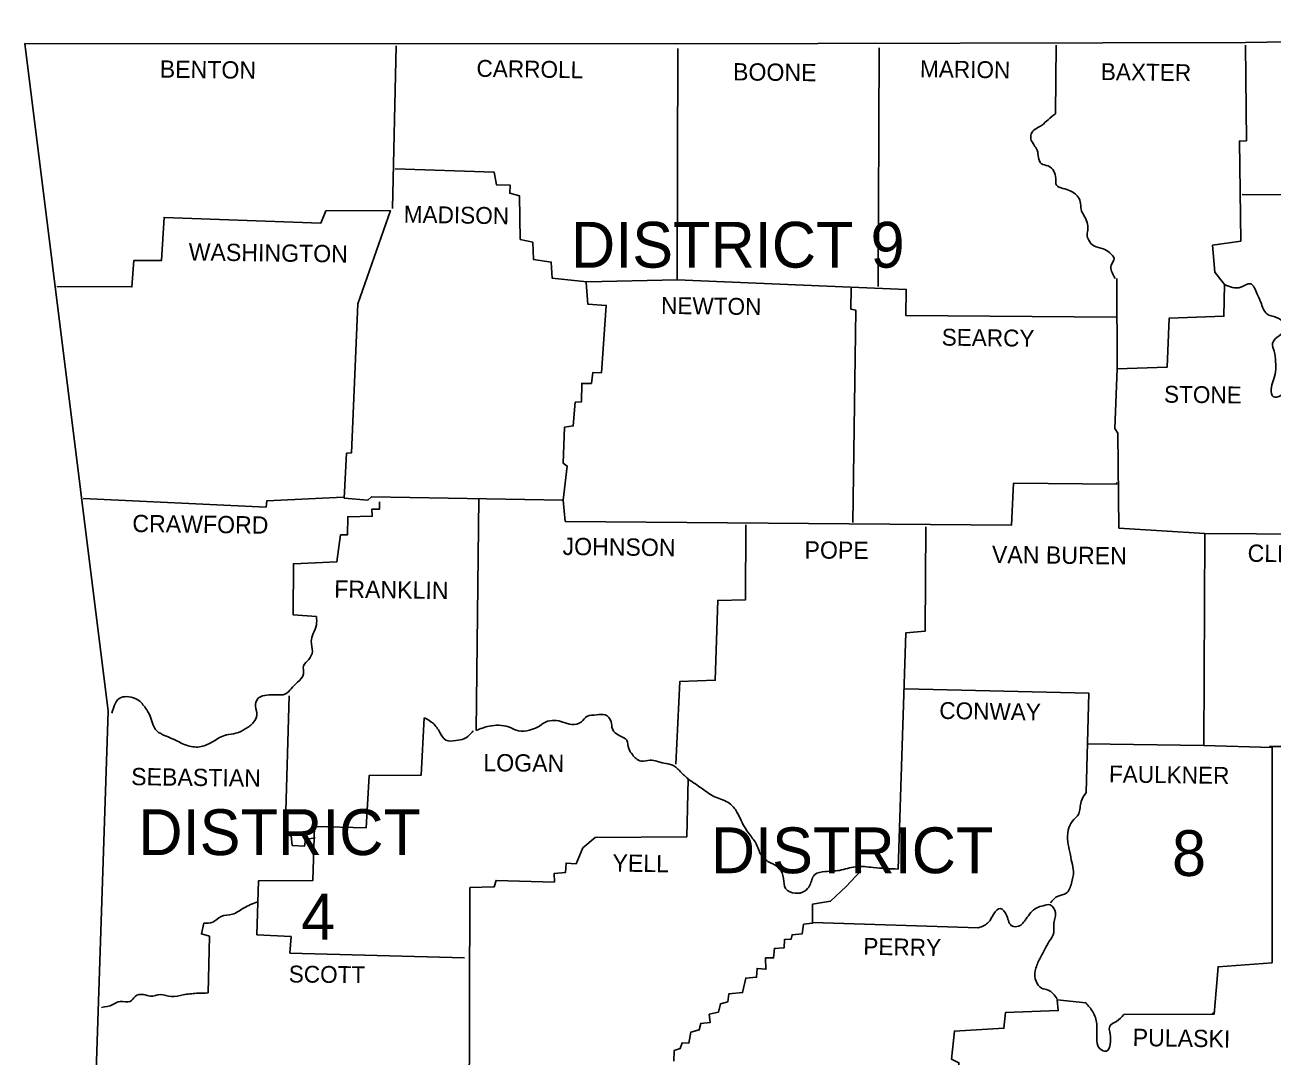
# Model space of a CAD drawing. Extents: x -33639 to 34530, y -17264 to 5867.
# Drawn here: x -17668 to -15961, y 4454 to 5867 of the extents above; entities that cross this region are included whole.
import ezdxf

# ---------------------------------------------------------------- set-up
doc = ezdxf.new("R2010")
doc.units = 0
for name, color, linetype in [('1', 7, 'Continuous'), ('2', 7, 'Continuous'), ('3', 7, 'Continuous')]:
    doc.layers.add(name, color=color, linetype=linetype)

msp = doc.modelspace()

# ---------------------------------------------------------------- linework, layer by layer
at = {"layer": '1'}
for points in [[(-17667.8, 5841.4), (-16777.9, 5840.9), (-15996.9, 5842.5), (-15075.6, 5856.8), (-14648.6, 5866.7)], [(-17667.8, 5841.4), (-17553.9, 4926.7), (-17603.4, 3433.6)], [(-16256.1, 5839.2), (-16257.2, 5745.1)], [(-15996.9, 5839.2), (-15995.8, 5708.2), (-16005.2, 5707.7), (-16003.5, 5570.7), (-16042.1, 5565.2), (-16038.8, 5528.3), (-16025.5, 5511.2), (-16026.6, 5467.7), (-16101.5, 5465), (-16104.2, 5397.8), (-16172.5, 5395.6), (-16175.8, 5314.2), (-16171.9, 5307.6), (-16170.3, 5177.7), (-16052.5, 5170), (-16054.2, 4880), (-15960.6, 4877.2), (-15960.6, 4582.2), (-16034.4, 4576.7), (-16039.9, 4511.8), (-16163.7, 4511.2)], [(-15530.8, 5847.5), (-15529.7, 5711), (-15601.2, 5707.1), (-15603.4, 5632.3), (-16001.3, 5634.5)], [(-17159.8, 5838.1), (-17164.8, 5615.2)], [(-17160.9, 5669.7), (-17025.5, 5665.3), (-17022.2, 5647.7), (-17003.5, 5647.2), (-17004.1, 5636.1), (-16990.9, 5632.8), (-16989.8, 5572.9), (-16972.7, 5569), (-16971.6, 5545.3), (-16947.4, 5542), (-16946.3, 5520), (-16898.4, 5515.1), (-16775.1, 5517.8), (-16774, 5834.3)], [(-16498.3, 5835.4), (-16500, 5508.5)], [(-17624.3, 5508.5), (-17521.4, 5507.9), (-17518.7, 5544.2), (-17480.7, 5544.2), (-17477.4, 5603.1), (-17262.7, 5595.4), (-17256.1, 5611.9), (-17167.5, 5612.5), (-17212.1, 5484.8), (-17220.9, 5280.6), (-17227.5, 5280.1), (-17230.8, 5218.4), (-17198.4, 5215.7), (-17193.4, 5220.6), (-16930.9, 5215.7), (-16928.1, 5186.5)], [(-16775.1, 5517.8), (-16461.4, 5504.6), (-16462, 5468.8), (-16174.1, 5466.6)], [(-16172.5, 5395.6), (-16173, 5519.5)], [(-16899.5, 5514), (-16897.3, 5484.3), (-16872, 5482.6), (-16878.6, 5390.1), (-16890.2, 5390.7), (-16892.4, 5375.8), (-16905.6, 5375.8), (-16906.1, 5350.5), (-16914.4, 5350), (-16917.1, 5317.5), (-16929.2, 5315.8), (-16930.9, 5266.3), (-16925.4, 5262.5), (-16930.9, 5215.7)], [(-16536.8, 5506.3), (-16537.4, 5477.6), (-16530.2, 5476), (-16534.6, 5185.4)], [(-16928.1, 5186.5), (-16317.2, 5181.6), (-16314.5, 5239.3), (-16172.5, 5237.7)], [(-16174.1, 5238.2), (-16172.5, 5239.9)], [(-17588, 5217.9), (-17337.6, 5206.3), (-17336.5, 5215.1), (-17231.9, 5220.1)], [(-17182.4, 5213.5), (-17182.4, 5203.6), (-17192.8, 5203.6), (-17192.3, 5193.7), (-17225.9, 5193.1), (-17226.4, 5168.3), (-17235.8, 5168.3), (-17240.7, 5131.5), (-17300.2, 5128.7), (-17300.7, 5058.8), (-17268.8, 5056.6)], [(-17046.5, 5217.9), (-17050.3, 4900.3)], [(-16681, 5182.1), (-16681.6, 5079.2), (-16719.5, 5078.6), (-16722.8, 4969.1), (-16771.3, 4967.5), (-16776.8, 4854.1)], [(-16434.5, 5179.4), (-16435.6, 5036.3), (-16462, 5034.1), (-16472.4, 4710.5)], [(-16052.5, 5170), (-15769.6, 5168.3), (-15745.4, 5179.9), (-15747.1, 4964.7), (-15763.6, 4957.6), (-15778.4, 4944.9), (-15783.4, 4940), (-15783.9, 4878.3), (-15963.9, 4878.3)], [(-16463.1, 4957.6), (-16211.6, 4951.5), (-16214.9, 4815.6)], [(-17306.2, 4947.7), (-17311.7, 4758.3), (-17303.5, 4756.1), (-17301.8, 4742.9), (-17285.3, 4741.8), (-17283.7, 4751.2), (-17270.4, 4753.4)], [(-17121.3, 4917.9), (-17125.2, 4839.2), (-17196.7, 4838.7), (-17200.6, 4767.1), (-17271.5, 4768.8), (-17273.7, 4695), (-17348, 4694.5), (-17350.2, 4620.7), (-17303.5, 4618), (-17305.1, 4595.4), (-17066.3, 4588.8)], [(-16214.3, 4882.2), (-16054.2, 4880)], [(-16759.7, 4833.7), (-16761.9, 4754.5), (-16887.4, 4753.9), (-16903.9, 4739.6), (-16913.3, 4717.6), (-16927, 4718.7), (-16927.6, 4706), (-16943.5, 4704.4), (-16943, 4692.8), (-17022.8, 4695), (-17025.5, 4686.2), (-17058.6, 4685.1), (-17059.7, 4363.2)], [(-16523.6, 4708.3), (-16543.4, 4686.8), (-16564.9, 4666.4), (-16589.7, 4662.6), (-16589.7, 4636.7), (-16601.8, 4635.1), (-16604, 4621.8), (-16617.7, 4620.7), (-16618.8, 4614.7), (-16628.2, 4614.1), (-16628.7, 4602.6), (-16641.9, 4602), (-16643, 4588.8), (-16654.1, 4588.8), (-16653.5, 4573.4), (-16665.6, 4574.5), (-16666.2, 4562.4), (-16681, 4561.3), (-16685.4, 4541.5), (-16704.1, 4539.8), (-16705.8, 4528.8), (-16715.7, 4526.1), (-16718.4, 4514.5), (-16731.1, 4511.8), (-16730, 4500.2), (-16742.7, 4499.1), (-16744.9, 4490.3), (-16756.4, 4487), (-16759.2, 4472.1), (-16768, 4472.7), (-16770.7, 4465), (-16779, 4462.2), (-16779.5, 4447.4)], [(-17416.8, 4540.9), (-17415.2, 4618.5), (-17426.2, 4621.8), (-17422.9, 4636.7)], [(-16362.4, 4630.1), (-16589.1, 4637.3)], [(-16215.4, 4527.2), (-16255, 4531.6), (-16253.4, 4516.7), (-16325.5, 4514), (-16327.7, 4492.5), (-16395.4, 4488.7), (-16399.2, 4450.1), (-16389.3, 4445.2), (-16389.3, 4420.6)], [(-16042.6, 4512.3), (-16039.9, 4515.1)]]:
    msp.add_lwpolyline(points, dxfattribs=at)
for points in [[(-16257.2, 5745.1), (-16267.2, 5736.9), (-16276, 5729.2), (-16289.2, 5719.8), (-16290.8, 5711), (-16286.4, 5702.2), (-16282, 5695), (-16280.4, 5685.1), (-16276.5, 5676.9), (-16267.2, 5673.6), (-16259.4, 5666.4), (-16256.7, 5656.5), (-16255.6, 5647.2), (-16246.8, 5642.8), (-16236.9, 5639.5), (-16227.5, 5632.8), (-16223.1, 5624.6), (-16222, 5614.1), (-16218.2, 5605.9), (-16213.8, 5596), (-16212.7, 5587.7), (-16213.8, 5579.5), (-16211.6, 5571.8), (-16204.4, 5564.1), (-16191.8, 5560.2), (-16182.9, 5554.7), (-16176.9, 5547), (-16180.7, 5537.6), (-16180.2, 5529.4), (-16175.2, 5519.5)], [(-16025.5, 5511.2), (-16003.5, 5507.4), (-15990.3, 5512.3), (-15981, 5498), (-15976, 5487), (-15967.8, 5471), (-15954.6, 5466.1), (-15944.6, 5457.3), (-15944.6, 5447.9), (-15953.4, 5439.1), (-15960.1, 5430.3), (-15957.9, 5419.9), (-15955.7, 5405.5), (-15955.7, 5391.8), (-15959, 5379.1), (-15961.7, 5367.6), (-15959, 5357.7), (-15948.5, 5359.3), (-15937.5, 5367.6), (-15925.9, 5367.6), (-15914.9, 5361.5), (-15903.4, 5351.1), (-15891.8, 5353.3), (-15882.5, 5356), (-15869.2, 5359.9), (-15859.9, 5354.9), (-15851.6, 5348.3), (-15841.7, 5337.9), (-15832.4, 5331.3), (-15820.3, 5325.2), (-15805.4, 5321.3), (-15791.6, 5312), (-15789.4, 5296), (-15790, 5282.3), (-15791.1, 5265.2), (-15792.2, 5246.5), (-15790.5, 5228.3), (-15784.5, 5216.2), (-15776.8, 5201.9), (-15774.6, 5188.7), (-15775.1, 5167.8)], [(-17268.8, 5056.6), (-17268.8, 5045.1), (-17273.2, 5033), (-17275.9, 5022.5), (-17274.3, 5008.7), (-17279.3, 4997.7), (-17286.4, 4988.9), (-17286.4, 4977.9), (-17294.7, 4966.4), (-17303.5, 4957.6), (-17311.2, 4950.4), (-17324.9, 4949.3), (-17336.5, 4948.8), (-17348, 4944.9), (-17352.4, 4936.6), (-17350.2, 4924), (-17354.7, 4911.9), (-17366.2, 4902.5), (-17378.9, 4896.5), (-17392.1, 4894.3), (-17410.2, 4885.5), (-17426.7, 4878.3), (-17444.4, 4879.4), (-17460.9, 4886.6), (-17475.7, 4893.2), (-17487.3, 4899.8), (-17496.6, 4920.1), (-17502.7, 4931.1), (-17513.2, 4942.2), (-17525.8, 4946.6), (-17536.3, 4945.5), (-17548.9, 4924)], [(-17121.3, 4917.9), (-17109.2, 4910.2), (-17099.8, 4897.6), (-17091.6, 4887.1), (-17077.8, 4886.6), (-17066.8, 4888.8), (-17054.2, 4899.8)], [(-17050.3, 4900.3), (-17032.1, 4906.4), (-17018.9, 4907.5), (-17005.7, 4905.3), (-16992, 4899.8), (-16977.1, 4900.9), (-16966.1, 4904.7), (-16955.1, 4911.9), (-16943, 4914.1), (-16931.4, 4911.9), (-16919.3, 4908.6), (-16906.1, 4912.4), (-16898.4, 4919.6), (-16885.2, 4921.8), (-16873.6, 4921.8), (-16865.4, 4912.4), (-16863.7, 4902.5), (-16853.3, 4893.2), (-16843.9, 4887.1), (-16841.2, 4875.6), (-16836.2, 4867.3), (-16831.3, 4861.8), (-16824.1, 4858.5), (-16812, 4859.6), (-16793.3, 4855.7), (-16781.2, 4853), (-16770.2, 4843.6), (-16759.7, 4833.7)], [(-16759.7, 4833.7), (-16740.5, 4820.5), (-16722.3, 4809), (-16703.6, 4800.7), (-16693.1, 4788.6), (-16683.8, 4769.9), (-16676.1, 4758.3), (-16666.2, 4744), (-16659, 4728.1), (-16647.4, 4719.3), (-16635.3, 4711.6), (-16629.3, 4697.8), (-16626.5, 4684), (-16613.3, 4677.4), (-16600.7, 4680.2), (-16593.5, 4688.4), (-16586.9, 4702.7), (-16572, 4707.2), (-16552.8, 4708.8), (-16530.8, 4713.8), (-16506.6, 4712.7), (-16472.4, 4710.5)], [(-16214.9, 4815.6), (-16222, 4802.9), (-16225.3, 4786.4), (-16234.1, 4775.9), (-16239.6, 4763.8), (-16240.2, 4747.9), (-16237.4, 4733.6), (-16234.7, 4719.8), (-16232.5, 4707.2), (-16235.2, 4691.2), (-16242.4, 4677.4), (-16253.4, 4673.6), (-16263.8, 4664.2)], [(-17422.9, 4636.7), (-17410.8, 4637.8), (-17399.2, 4645.5), (-17383.8, 4648.8), (-17368.4, 4657.1), (-17349.1, 4665.9)], [(-16362.4, 4630.1), (-16348.6, 4637.8), (-16341.4, 4649.4), (-16332.6, 4656.5), (-16323.8, 4646.6), (-16316.1, 4632.3), (-16307.9, 4632.3), (-16297.4, 4642.2), (-16290.8, 4651), (-16282.6, 4657.6), (-16273.8, 4660.4), (-16264.4, 4661.5), (-16257.2, 4651), (-16259.4, 4634.5), (-16259.4, 4623.5), (-16265.5, 4611.9), (-16272.1, 4599.8), (-16279.3, 4586.1), (-16284.8, 4571.2), (-16283.7, 4556.9), (-16276, 4547.5), (-16267.2, 4544.8), (-16255, 4532.7)], [(-17416.8, 4540.9), (-17432.8, 4540.4), (-17451, 4538.2), (-17467.5, 4536), (-17482.3, 4538.7), (-17496.1, 4536.5), (-17505.4, 4538.7), (-17517, 4536), (-17523.6, 4529.4), (-17537.4, 4529.4), (-17547.3, 4525), (-17563.2, 4521.1)], [(-16215.4, 4527.2), (-16206.1, 4515.1), (-16200.6, 4498.6), (-16200.6, 4479.9), (-16196.2, 4464.4), (-16187.4, 4461.1), (-16181.8, 4474.4), (-16182.9, 4487.6), (-16182.9, 4495.3), (-16173.6, 4501.9), (-16163.7, 4511.2)]]:
    msp.add_spline(points, degree=3, dxfattribs=at)

# ---------------------------------------------------------------- texts
at = {"layer": '2'}
for s, height, rotation, p in [('BENTON', 23.67, 359.2527, (-17483.4, 5794.6)), ('CARROLL', 23.11, 359.1481, (-17049.8, 5795.8)), ('BOONE', 23.67, 359.4001, (-16698.6, 5790.8)), ('MARION', 23.11, 359.1854, (-16442.7, 5795.2)), ('BAXTER', 23.11, 359.2559, (-16195.1, 5791.3)), ('MADISON', 23.11, 359.0906, (-17149.4, 5596)), ('WASHINGTON', 23.66, 359.232, (-17443.8, 5544.2)), ('NEWTON', 23.11, 359.2717, (-16797.1, 5471)), ('SEARCY', 23.11, 359.2527, (-16413, 5427.6)), ('STONE', 23.11, 359.4001, (-16108.6, 5349.4)), ('CRAWFORD', 23.66, 359.2771, (-17520.9, 5172.2)), ('JOHNSON', 23.67, 359.3514, (-16932, 5140.8)), ('POPE', 23.67, 359.6155, (-16600.7, 5135.9)), ('VAN BUREN', 23.67, 359.3508, (-16344.2, 5129.8)), ('CLEBURNE', 23.66, 359.2535, (-15994.2, 5131.5)), ('FRANKLIN', 23.67, 359.1815, (-17244.6, 5082.5)), ('CONWAY', 23.11, 359.0371, (-16416.3, 4916.3)), ('LOGAN', 23.67, 359.3969, (-17040.4, 4844.7)), ('SEBASTIAN', 23.66, 359.2816, (-17522.5, 4825.5)), ('FAULKNER', 23.11, 359.2486, (-16184, 4829.3)), ('YELL', 23.67, 359.1987, (-16863.7, 4707.2)), ('PERRY', 23.11, 359.0858, (-16520.3, 4593.2)), ('SCOTT', 23.11, 359.4063, (-17306.8, 4555.3)), ('PULASKI', 23.67, 359.053, (-16151.6, 4468.3))]:
    msp.add_text(s, height=height, rotation=rotation, dxfattribs=at).set_placement(p)
at = {"layer": '3'}
for s, height, p in [('DISTRICT 9', 62.74, (-16920.4, 5534.3)), ('DISTRICT', 62.74, (-17512.6, 4729.7)), ('DISTRICT', 62.74, (-16728.9, 4704.9)), ('8', 62.7, (-16097.6, 4701.1)), ('4', 62.7, (-17289.7, 4614.1))]:
    msp.add_text(s, height=height, dxfattribs=at).set_placement(p)

doc.saveas('drawing.dxf')
